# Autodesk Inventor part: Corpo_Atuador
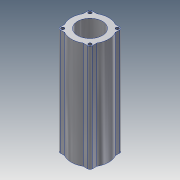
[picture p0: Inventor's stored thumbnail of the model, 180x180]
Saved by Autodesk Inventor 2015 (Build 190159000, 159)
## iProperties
Created: 2015-04
Part Number: Corpo_Atuador
Material: Aluminum 6061
Document SubType Name: Modeling
Designer: TREINA6
Density: 2.7 g/cm^3
Appearance: Aluminum - Flat
Author: TREINA6
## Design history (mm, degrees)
sketch "Sketch1"
  geometry: L1 (-32.5, -32.5)-(32.5, -32.5); L2 (32.5, -32.5)-(32.5, 32.5); L3 (32.5, 32.5)-(-32.5, 32.5); L4 (-32.5, 32.5)-(-32.5, -32.5); L5 (-32.5, -32.5)-(32.5, 32.5); L6 (32.5, -32.5)-(-32.5, 32.5); C1 r 37.5 at (0, 0); 1 further point
  constraints: 12 end point, 2 midpoint, 2 parallel, 1 centre point, 1 coincident, 1 horizontal, 1 perpendicular
  dimensions: "d0" = 65 distance of L3.end L2.end; "d1" = 65 distance of L2.end L1.end; "d2" = 75 diameter of C1
extrude "Extrusion1" new body sketch "Sketch1" distance "d3" = 15; taper "d4" = 0 deg
extrude "Extrusion2" join sketch "Sketch1" distance "d5" = 230; taper "d7" = 0 deg; dims "d6" = 15, "d8" = 0
sketch "Sketch2"
  geometry: L1 (-32.5, -32.5)-(-18.708, -32.5) reference; L2 (32.5, -32.5)-(32.5, -18.708) reference; L3 (32.5, 32.5)-(18.708, 32.5) reference; L4 (-32.5, 32.5)-(-32.5, 18.708) reference; L5 (-32.5, -18.708)-(-32.5, -32.5) reference; L6 (18.708, -32.5)-(32.5, -32.5) reference; L7 (32.5, 18.708)-(32.5, 32.5) reference; L8 (-18.708, 32.5)-(-32.5, 32.5) reference; A1 r 37.5 centre (0, 0) between (32.5, 18.708) and (18.708, 32.5) reference; A2 r 37.5 centre (0, 0) between (-32.5, -18.708) and (-18.708, -32.5) reference; A3 r 37.5 centre (0, 0) between (18.708, -32.5) and (32.5, -18.708) reference; A4 r 37.5 centre (0, 0) between (-18.708, 32.5) and (-32.5, 18.708) reference; 1 further point
extrude "Extrusion3" join sketch "Sketch2" distance "d9" = 15; taper "d10" = 0 deg
fillet "Fillet1" dims "d11" = 5
sketch "Sketch3"
  geometry: L1 (18.708, -32.5)-(27.5, -32.5) reference; L2 (32.5, -27.5)-(32.5, -18.708) reference; L3 (-27.5, -32.5)-(-18.708, -32.5) reference; L4 (-32.5, -18.708)-(-32.5, -27.5) reference; L5 (27.5, 32.5)-(18.708, 32.5) reference; L6 (32.5, 18.708)-(32.5, 27.5) reference; L7 (-32.5, 27.5)-(-32.5, 18.708) reference; L8 (-18.708, 32.5)-(-27.5, 32.5) reference; A1 r 5 centre (27.5, -27.5) between (27.5, -32.5) and (32.5, -27.5) reference; A2 r 37.5 centre (0, 0) between (-32.5, -18.708) and (-18.708, -32.5) reference; A3 r 5 centre (-27.5, -27.5) between (-32.5, -27.5) and (-27.5, -32.5) reference; A4 r 37.5 centre (0, 0) between (18.708, -32.5) and (32.5, -18.708) reference; A5 r 5 centre (27.5, 27.5) between (32.5, 27.5) and (27.5, 32.5) reference; A6 r 37.5 centre (0, 0) between (32.5, 18.708) and (18.708, 32.5) reference; A7 r 5 centre (-27.5, 27.5) between (-27.5, 32.5) and (-32.5, 27.5) reference; A8 r 37.5 centre (0, 0) between (-18.708, 32.5) and (-32.5, 18.708) reference; 1 further point
  node "Projected Loop2"
sketch "Sketch4"
  geometry: L1 (27.5, -32.5)-(18.708, -32.5) reference; L2 (32.5, 27.5)-(32.5, 18.708) reference; L3 (18.708, 32.5)-(27.5, 32.5) reference; L4 (-27.5, 32.5)-(-18.708, 32.5) reference; L5 (-32.5, 18.708)-(-32.5, 27.5) reference; L6 (32.5, -18.708)-(32.5, -27.5) reference; L7 (-32.5, -27.5)-(-32.5, -18.708) reference; L8 (-18.708, -32.5)-(-27.5, -32.5) reference; C1 r 5 at (-27.5, 27.5); A1 r 5 centre (27.5, -27.5) between (27.5, -32.5) and (32.5, -27.5) reference; A2 r 37.5 centre (0, 0) between (18.708, -32.5) and (32.5, -18.708) reference; A3 r 37.5 centre (0, 0) between (32.5, -18.708) and (32.5, 18.708) reference; A4 r 5 centre (27.5, 27.5) between (32.5, 27.5) and (27.5, 32.5) reference; A5 r 37.5 centre (0, 0) between (18.708, 32.5) and (-18.708, 32.5) reference; A6 r 5 centre (-27.5, 27.5) between (-27.5, 32.5) and (-32.5, 27.5) reference; A7 r 37.5 centre (0, 0) between (-32.5, 18.708) and (-32.5, -18.708) reference; A8 r 37.5 centre (0, 0) between (-32.5, -18.708) and (-18.708, -32.5) reference; A9 r 37.5 centre (0, 0) between (-18.708, -32.5) and (18.708, -32.5) reference; A10 r 37.5 centre (0, 0) between (32.5, 18.708) and (18.708, 32.5) reference; A11 r 37.5 centre (0, 0) between (-18.708, 32.5) and (-32.5, 18.708) reference; A12 r 5 centre (-27.5, -27.5) between (-32.5, -27.5) and (-27.5, -32.5) reference; 1 further point
  constraints: 1 centre point, 1 coincident, 1 concentric
extrude "Extrusion4" join sketch "Sketch4" distance "d12" = 219.75; taper "d13" = 0 deg
hole "Hole1" diameter "d16" = 50; stored, may be unused: countersink angle "d20" = 90 deg, drill point angle "d22" = 0 deg; dims "d14" = 10, "d15" = 10, "d17" = 6, "d18" = 4, "d19" = 2, "d21" = 230
node "Direct Edit1"
hole "Hole2" diameter "d31" = 6.647; stored, may be unused: countersink angle "d35" = 90 deg, drill point angle "d37" = 0 deg; dims "d29" = 10, "d30" = 10, "d32" = 16, "d33" = 4, "d34" = 2, "d36" = 22.2
pattern_circular "Circular Pattern1" dims angle "d39" = 360 deg
body "Solid1"
node "Projected Loop1"
node "Project Cut Edges1"
move_body "Move1" dims "d25" = -15
move_body "Move2" dims "d28" = -15
other parameters: "d23" = 0, "d24" = 0, "d26" = 0, "d27" = 0
